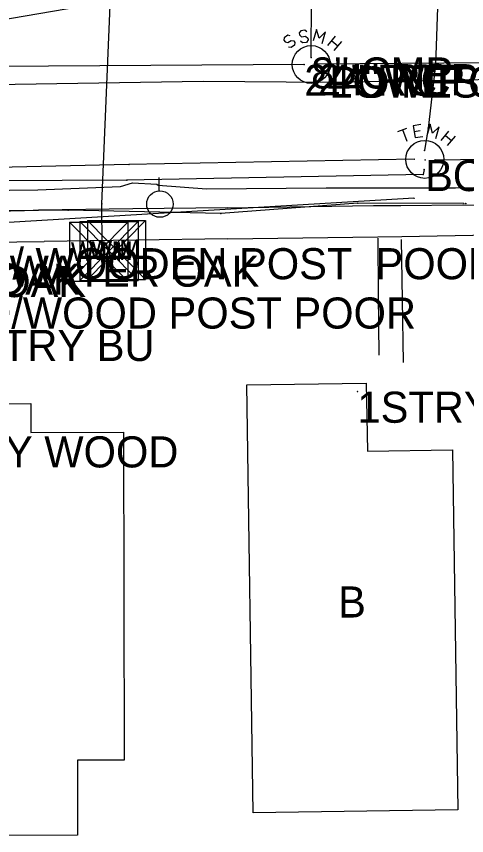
# Model space of a CAD drawing. Extents: x 1304270 to 1306561, y 1876019 to 1876752.
# Drawn here: x 1306184.9 to 1306257.2, y 1876292.6 to 1876424.3 of the extents above; entities that cross this region are included whole.
import ezdxf

# ---------------------------------------------------------------- set-up
doc = ezdxf.new("R2010")
doc.units = 0
for name, color, linetype in [('Default', 7, 'Continuous'), ('S_BUILDING', 7, 'Continuous'), ('S_BUILDING_ANNOT', 7, 'Continuous'), ('S_EDGE_PAVEMENT', 7, 'Continuous'), ('S_ELECTRIC_UTILITIES_ANNOT', 7, 'Continuous'), ('S_FENCE_ANNOT', 7, 'Continuous'), ('S_FIBER_OPTIC_CABLE', 7, 'Continuous'), ('S_GAS_UTILITIES', 7, 'Continuous'), ('S_MANHOLE_ANNOT', 7, 'Continuous'), ('S_MSC_PT_SYM', 7, 'Continuous'), ('S_PAVEMENT_CROWN', 7, 'Continuous'), ('S_SANITARY_SEWER', 7, 'Continuous'), ('S_SANITARY_SEWER_ANNOT', 7, 'Continuous'), ('S_SIDEWALK', 7, 'Continuous'), ('S_SURVEY_TEXT_ANNOT', 7, 'Continuous'), ('S_TELEPHONE_UTILITIES_ANNOT', 7, 'Continuous'), ('S_TREE_ANNOT', 7, 'Continuous'), ('S_UTILITY_POLE', 7, 'Continuous'), ('S_UTL_PT_SYM', 7, 'Continuous'), ('S_WATER_UTILITIES', 7, 'Continuous')]:
    doc.layers.add(name, color=color, linetype=linetype)

msp = doc.modelspace()

# ---------------------------------------------------------------- linework, layer by layer
at = {"layer": 'Default'}
msp.add_line((1305993.25, 1876391.55), (1306312.09, 1876445.88), dxfattribs=at)
at = {"layer": 'S_BUILDING'}
for points in [[(1306222.87, 1876296.29), (1306221.85, 1876365.09), (1306241.06, 1876365.38), (1306241.23, 1876354.44), (1306254.91, 1876354.64), (1306255.77, 1876296.78)], [(1306160.27, 1876302.99), (1306160.13, 1876356.76), (1306176.97, 1876356.8), (1306176.96, 1876362.05), (1306187.16, 1876362.08), (1306187.17, 1876357.43), (1306202.04, 1876357.47), (1306202.18, 1876304.76), (1306194.65, 1876304.74), (1306194.68, 1876292.7), (1306165.2, 1876292.62), (1306165.17, 1876303)]]:
    msp.add_lwpolyline(points, close=True, dxfattribs=at)
at = {"layer": 'S_EDGE_PAVEMENT'}
msp.add_lwpolyline([(1306165.48, 1876396.19), (1306188.31, 1876396.43), (1306201.55, 1876396.99), (1306203.51, 1876397.54), (1306207.41, 1876397.36), (1306207.63, 1876397.16), (1306215.41, 1876396.62), (1306234.61, 1876396.75), (1306255.38, 1876396.73), (1306279.47, 1876397.14), (1306280.07, 1876397.39), (1306281.48, 1876397.3), (1306281.94, 1876397.15), (1306288.47, 1876397.22), (1306311.84, 1876397.17), (1306330.84, 1876397.38), (1306332.77, 1876398.02), (1306334.38, 1876398.14), (1306335.31, 1876398.67), (1306336.28, 1876398.38), (1306337.28, 1876397.24), (1306338.63, 1876397.21), (1306354.54, 1876397.37)], dxfattribs=at)
at = {"layer": 'S_FIBER_OPTIC_CABLE'}
for p, q in [((1306252.78, 1876433.33), (1306252.18, 1876416.51)), ((1306252.18, 1876416.51), (1306251.01, 1876406.35)), ((1306251.01, 1876406.35), (1306250.43, 1876402.76)), ((1306248.77, 1876401.37), (1306202.94, 1876400.5)), ((1306252.11, 1876401.25), (1306297.1, 1876401.93)), ((1306202.94, 1876400.5), (1306143.64, 1876399.14)), ((1306250.33, 1876399.72), (1306250.18, 1876398.92)), ((1306250.18, 1876398.92), (1306202.59, 1876398)), ((1306202.59, 1876398), (1306143.62, 1876397.73)), ((1306248.72, 1876395.07), (1306106.88, 1876386.6))]:
    msp.add_line(p, q, dxfattribs=at)
at = {"layer": 'S_GAS_UTILITIES'}
for p, q in [((1306239.69, 1876394.28), (1306217.67, 1876392.63)), ((1306256.71, 1876394.26), (1306239.69, 1876394.28)), ((1306193.15, 1876393.15), (1306132.81, 1876392.65)), ((1306217.67, 1876392.63), (1306193.15, 1876393.15))]:
    msp.add_line(p, q, dxfattribs=at)
at = {"layer": 'S_MSC_PT_SYM'}
for points in [[(1306235.12, 1876416.26), (1306235.12, 1876416.31), (1306235.12, 1876416.26), (1306235.07, 1876416.26), (1306235.12, 1876416.26), (1306235.12, 1876416.21), (1306235.12, 1876416.26), (1306235.17, 1876416.26)], [(1306257.03, 1876394.23), (1306257.03, 1876394.28), (1306257.03, 1876394.23), (1306256.98, 1876394.23), (1306257.03, 1876394.23), (1306257.03, 1876394.18), (1306257.03, 1876394.23), (1306257.08, 1876394.23)], [(1306239.64, 1876363.99), (1306239.64, 1876364.04), (1306239.64, 1876363.99), (1306239.59, 1876363.99), (1306239.64, 1876363.99), (1306239.64, 1876363.94), (1306239.64, 1876363.99), (1306239.69, 1876363.99)]]:
    msp.add_lwpolyline(points, dxfattribs=at)
at = {"layer": 'S_PAVEMENT_CROWN'}
msp.add_lwpolyline([(1306053.64, 1876411.74), (1306078.45, 1876411.98), (1306096.34, 1876412.19), (1306114.22, 1876412.39), (1306129.3, 1876412.61), (1306144.38, 1876412.83), (1306159.45, 1876413.06), (1306174.53, 1876413.28), (1306194.7, 1876413.58), (1306214.87, 1876413.88), (1306234.9, 1876413.74), (1306250.98, 1876414.03), (1306267.06, 1876414.33), (1306289.97, 1876414.14), (1306302.49, 1876414.59), (1306315, 1876415.05), (1306334.8, 1876415.21), (1306354.59, 1876415.38)], dxfattribs=at)
at = {"layer": 'S_SANITARY_SEWER'}
for p, q in [((1306232.19, 1876417.72), (1306232.35, 1876438.98)), ((1306227.88, 1876420.88), (1306227.81, 1876420.49)), ((1306227.81, 1876420.49), (1306228, 1876420.22)), ((1306228.43, 1876421.27), (1306227.88, 1876420.88)), ((1306228.85, 1876421.19), (1306228.43, 1876421.27)), ((1306234.86, 1876419.64), (1306236.1, 1876421.11)), ((1306228, 1876420.22), (1306228.43, 1876420.1)), ((1306228.43, 1876420.1), (1306228.97, 1876420.45)), ((1306228.97, 1876419.29), (1306228.58, 1876419.37)), ((1306228.97, 1876420.45), (1306229.43, 1876420.37)), ((1306229.51, 1876419.68), (1306228.97, 1876419.29)), ((1306229.43, 1876420.37), (1306229.59, 1876420.1)), ((1306229.59, 1876420.1), (1306229.51, 1876419.68)), ((1306235.52, 1876420.41), (1306236.49, 1876419.6)), ((1306237.07, 1876420.3), (1306235.83, 1876418.82)), ((1306231.1, 1876416.56), (1305933.99, 1876414.7)), ((1306295.77, 1876417.07), (1306233.29, 1876416.64))]:
    msp.add_line(p, q, dxfattribs=at)
for points in [[(1306231.53, 1876421.81), (1306231.18, 1876422.08), (1306230.52, 1876422), (1306230.29, 1876421.65), (1306230.33, 1876421.34), (1306230.67, 1876421.03), (1306231.29, 1876421.15), (1306231.68, 1876420.84), (1306231.72, 1876420.53), (1306231.45, 1876420.14), (1306230.83, 1876420.06), (1306230.48, 1876420.34)], [(1306233.97, 1876419.95), (1306234.51, 1876421.81), (1306233.46, 1876420.8), (1306233.08, 1876422.23), (1306232.53, 1876420.37)]]:
    msp.add_lwpolyline(points, dxfattribs=at)
msp.add_circle((1306232.21, 1876416.58), 3.05, dxfattribs=at)
at = {"layer": 'S_SIDEWALK'}
for points in [[(1305952.26, 1876390.24), (1305960.41, 1876390.32), (1305966.26, 1876390.42), (1305977.98, 1876390.44), (1306001.88, 1876390.73), (1306025.78, 1876391.03), (1306046.11, 1876391.23), (1306059.51, 1876391.31), (1306072.82, 1876391.56), (1306093.38, 1876391.82), (1306107.91, 1876392.05), (1306108.42, 1876392.1), (1306122.83, 1876392.12), (1306134.63, 1876392.34), (1306141.58, 1876392.5), (1306158.19, 1876392.68), (1306174.81, 1876392.86), (1306188.4, 1876393.18)], [(1306218.73, 1876393.56), (1306203.56, 1876393.37), (1306188.4, 1876393.18)], [(1306218.73, 1876393.56), (1306242.23, 1876393.89), (1306246.62, 1876393.94), (1306256.53, 1876394.01), (1306278.18, 1876393.8), (1306278.83, 1876393.36), (1306281.72, 1876391.3), (1306281.69, 1876389.49)], [(1306218.81, 1876388.57), (1306242.93, 1876388.89), (1306246.78, 1876388.93), (1306260.98, 1876389.2), (1306270.25, 1876389.34), (1306277.02, 1876389.42), (1306281.65, 1876389.43)], [(1305946.19, 1876385.43), (1305960.07, 1876385.78), (1305966.36, 1876385.64), (1305978.22, 1876385.78), (1305997.78, 1876385.93), (1306001.65, 1876386), (1306023.78, 1876386.14), (1306028.37, 1876386.22), (1306037.11, 1876386.23), (1306046.79, 1876386.36), (1306058.81, 1876386.53), (1306072.25, 1876386.67), (1306085.1, 1876386.45), (1306093.62, 1876386.85), (1306109.56, 1876387.13), (1306122.97, 1876387.27), (1306134.64, 1876387.44), (1306141.92, 1876387.73), (1306161.2, 1876387.87), (1306180.48, 1876388.02), (1306189.34, 1876388.14)], [(1306218.81, 1876388.57), (1306204.07, 1876388.36), (1306189.34, 1876388.14)], [(1306242.9, 1876388.68), (1306242.95, 1876379.67), (1306243.09, 1876369.83)], [(1306247.03, 1876368.68), (1306246.89, 1876378.75), (1306246.73, 1876388.47)]]:
    msp.add_lwpolyline(points, dxfattribs=at)
at = {"layer": 'S_TELEPHONE_UTILITIES_ANNOT'}
for p, q in [((1306246.12, 1876405.82), (1306247.56, 1876406.37)), ((1306246.86, 1876406.13), (1306247.56, 1876404.27)), ((1306249.81, 1876406.95), (1306248.57, 1876406.71)), ((1306248.57, 1876406.71), (1306248.91, 1876404.82)), ((1306249.69, 1876405.94), (1306248.76, 1876405.78)), ((1306248.91, 1876404.82), (1306250.15, 1876405.01)), ((1306253.1, 1876404.39), (1306254.34, 1876405.86)), ((1306253.76, 1876405.16), (1306254.73, 1876404.35)), ((1306255.31, 1876405.05), (1306254.07, 1876403.58))]:
    msp.add_line(p, q, dxfattribs=at)
msp.add_lwpolyline([(1306252.21, 1876404.7), (1306252.75, 1876406.56), (1306251.7, 1876405.55), (1306251.32, 1876406.99), (1306250.77, 1876405.13)], dxfattribs=at)
msp.add_circle((1306250.45, 1876401.33), 3.05, dxfattribs=at)
at = {"layer": 'S_UTILITY_POLE'}
msp.add_line((1306207.79, 1876396.3), (1306207.79, 1876398.4), dxfattribs=at)
msp.add_circle((1306207.91, 1876394.15), 2.13, dxfattribs=at)
at = {"layer": 'S_UTL_PT_SYM'}
for points in [[(1306231.1, 1876416.56), (1306231.1, 1876416.61), (1306231.1, 1876416.56), (1306231.05, 1876416.56), (1306231.1, 1876416.56), (1306231.1, 1876416.51), (1306231.1, 1876416.56), (1306231.15, 1876416.56)], [(1306232.19, 1876417.72), (1306232.19, 1876417.77), (1306232.19, 1876417.72), (1306232.14, 1876417.72), (1306232.19, 1876417.72), (1306232.19, 1876417.67), (1306232.19, 1876417.72), (1306232.24, 1876417.72)], [(1306233.29, 1876416.64), (1306233.29, 1876416.69), (1306233.29, 1876416.64), (1306233.24, 1876416.64), (1306233.29, 1876416.64), (1306233.29, 1876416.59), (1306233.29, 1876416.64), (1306233.34, 1876416.64)], [(1306252.18, 1876416.51), (1306252.18, 1876416.56), (1306252.18, 1876416.51), (1306252.13, 1876416.51), (1306252.18, 1876416.51), (1306252.18, 1876416.46), (1306252.18, 1876416.51), (1306252.23, 1876416.51)], [(1306232.19, 1876416.37), (1306232.19, 1876416.42), (1306232.19, 1876416.37), (1306232.14, 1876416.37), (1306232.19, 1876416.37), (1306232.19, 1876416.32), (1306232.19, 1876416.37), (1306232.24, 1876416.37)], [(1306235.12, 1876416.26), (1306235.12, 1876416.31), (1306235.12, 1876416.26), (1306235.07, 1876416.26), (1306235.12, 1876416.26), (1306235.12, 1876416.21), (1306235.12, 1876416.26), (1306235.17, 1876416.26)], [(1306251.01, 1876406.35), (1306251.01, 1876406.4), (1306251.01, 1876406.35), (1306250.96, 1876406.35), (1306251.01, 1876406.35), (1306251.01, 1876406.3), (1306251.01, 1876406.35), (1306251.06, 1876406.35)], [(1306250.43, 1876402.76), (1306250.43, 1876402.81), (1306250.43, 1876402.76), (1306250.38, 1876402.76), (1306250.43, 1876402.76), (1306250.43, 1876402.71), (1306250.43, 1876402.76), (1306250.48, 1876402.76)], [(1306248.77, 1876401.37), (1306248.77, 1876401.42), (1306248.77, 1876401.37), (1306248.72, 1876401.37), (1306248.77, 1876401.37), (1306248.77, 1876401.32), (1306248.77, 1876401.37), (1306248.82, 1876401.37)], [(1306250.51, 1876401.23), (1306250.51, 1876401.28), (1306250.51, 1876401.23), (1306250.46, 1876401.23), (1306250.51, 1876401.23), (1306250.51, 1876401.18), (1306250.51, 1876401.23), (1306250.56, 1876401.23)], [(1306252.11, 1876401.25), (1306252.11, 1876401.3), (1306252.11, 1876401.25), (1306252.06, 1876401.25), (1306252.11, 1876401.25), (1306252.11, 1876401.2), (1306252.11, 1876401.25), (1306252.16, 1876401.25)], [(1306202.94, 1876400.5), (1306202.94, 1876400.55), (1306202.94, 1876400.5), (1306202.89, 1876400.5), (1306202.94, 1876400.5), (1306202.94, 1876400.45), (1306202.94, 1876400.5), (1306202.99, 1876400.5)], [(1306250.33, 1876399.72), (1306250.33, 1876399.77), (1306250.33, 1876399.72), (1306250.28, 1876399.72), (1306250.33, 1876399.72), (1306250.33, 1876399.67), (1306250.33, 1876399.72), (1306250.38, 1876399.72)], [(1306250.18, 1876398.92), (1306250.18, 1876398.97), (1306250.18, 1876398.92), (1306250.13, 1876398.92), (1306250.18, 1876398.92), (1306250.18, 1876398.87), (1306250.18, 1876398.92), (1306250.23, 1876398.92)], [(1306202.59, 1876398), (1306202.59, 1876398.05), (1306202.59, 1876398), (1306202.54, 1876398), (1306202.59, 1876398), (1306202.59, 1876397.95), (1306202.59, 1876398), (1306202.64, 1876398)], [(1306198.6, 1876394.2), (1306198.6, 1876394.25), (1306198.6, 1876394.2), (1306198.55, 1876394.2), (1306198.6, 1876394.2), (1306198.6, 1876394.15), (1306198.6, 1876394.2), (1306198.65, 1876394.2)], [(1306239.69, 1876394.28), (1306239.69, 1876394.33), (1306239.69, 1876394.28), (1306239.64, 1876394.28), (1306239.69, 1876394.28), (1306239.69, 1876394.23), (1306239.69, 1876394.28), (1306239.74, 1876394.28)], [(1306248.72, 1876395.07), (1306248.72, 1876395.12), (1306248.72, 1876395.07), (1306248.67, 1876395.07), (1306248.72, 1876395.07), (1306248.72, 1876395.02), (1306248.72, 1876395.07), (1306248.77, 1876395.07)], [(1306256.71, 1876394.26), (1306256.71, 1876394.31), (1306256.71, 1876394.26), (1306256.66, 1876394.26), (1306256.71, 1876394.26), (1306256.71, 1876394.21), (1306256.71, 1876394.26), (1306256.76, 1876394.26)], [(1306193.15, 1876393.15), (1306193.15, 1876393.2), (1306193.15, 1876393.15), (1306193.1, 1876393.15), (1306193.15, 1876393.15), (1306193.15, 1876393.1), (1306193.15, 1876393.15), (1306193.2, 1876393.15)], [(1306217.67, 1876392.63), (1306217.67, 1876392.68), (1306217.67, 1876392.63), (1306217.62, 1876392.63), (1306217.67, 1876392.63), (1306217.67, 1876392.58), (1306217.67, 1876392.63), (1306217.72, 1876392.63)], [(1306198.65, 1876387.44), (1306198.65, 1876387.49), (1306198.65, 1876387.44), (1306198.6, 1876387.44), (1306198.65, 1876387.44), (1306198.65, 1876387.39), (1306198.65, 1876387.44), (1306198.7, 1876387.44)]]:
    msp.add_lwpolyline(points, dxfattribs=at)
at = {"layer": 'S_WATER_UTILITIES'}
for p, q in [((1306198.6, 1876394.2), (1306200.22, 1876433.94)), ((1306198.65, 1876387.44), (1306198.6, 1876394.2)), ((1306196.26, 1876391.52), (1306205.6, 1876391.52)), ((1306196.26, 1876391.52), (1306196.26, 1876382.03)), ((1306196.26, 1876391.52), (1306205.6, 1876382.03)), ((1306205.6, 1876391.52), (1306196.26, 1876382.03)), ((1306205.6, 1876391.52), (1306205.6, 1876382.03)), ((1306193.39, 1876391.23), (1306202.73, 1876391.23)), ((1306193.39, 1876391.23), (1306193.39, 1876381.74)), ((1306193.39, 1876391.23), (1306202.73, 1876381.74)), ((1306202.73, 1876391.23), (1306193.39, 1876381.74)), ((1306195.06, 1876391.36), (1306204.4, 1876391.36)), ((1306195.06, 1876391.36), (1306195.06, 1876381.87)), ((1306195.06, 1876391.36), (1306204.4, 1876381.87)), ((1306204.4, 1876391.36), (1306195.06, 1876381.87)), ((1306202.73, 1876391.23), (1306202.73, 1876381.74)), ((1306204.4, 1876391.36), (1306204.4, 1876381.87)), ((1306193.39, 1876381.74), (1306202.73, 1876381.74)), ((1306195.06, 1876381.87), (1306204.4, 1876381.87)), ((1306196.26, 1876382.03), (1306205.6, 1876382.03))]:
    msp.add_line(p, q, dxfattribs=at)

# ---------------------------------------------------------------- texts
at = {"layer": 'S_BUILDING_ANNOT'}
for s, p in [('1 STRY WOOD', (1306164.07, 1876351.81)), ('B', (1306236.53, 1876327.68))]:
    msp.add_text(s, height=5, dxfattribs=at).set_placement(p)
at = {"layer": 'S_ELECTRIC_UTILITIES_ANNOT'}
msp.add_text('POINT ON ROAD UNDER LOW L', height=5, dxfattribs=at).set_placement((1306235.12, 1876411.26))
at = {"layer": 'S_FENCE_ANNOT'}
for s, p in [("3'WOODEN/ WOODEN POST  POOR", (1306148.39, 1876382.06)), ("2' WOOD/WOOD POST POOR", (1306155.64, 1876374.13))]:
    msp.add_text(s, height=5, dxfattribs=at).set_placement(p)
at = {"layer": 'S_MANHOLE_ANNOT'}
msp.add_text('BOTTOM OD HT', height=5, dxfattribs=at).set_placement((1306250.51, 1876396.23))
at = {"layer": 'S_SANITARY_SEWER_ANNOT'}
for s, p in [('24" RCP', (1306231.1, 1876411.56)), ('8" CMP', (1306232.19, 1876412.72)), ('24" RCP', (1306233.29, 1876411.64))]:
    msp.add_text(s, height=5, dxfattribs=at).set_placement(p)
at = {"layer": 'S_SURVEY_TEXT_ANNOT'}
for s, p in [('LOWEST UTILITY LINE', (1306235.12, 1876411.26)), ('ASPH DW TO 2 STRY BU', (1306128.29, 1876368.92)), ('1STRY BRICK', (1306239.64, 1876358.99))]:
    msp.add_text(s, height=5, dxfattribs=at).set_placement(p)
at = {"layer": 'S_TREE_ANNOT'}
for s, p in [('SPLIT 12" WATER OAK', (1306151.66, 1876380.86)), ('18" WATER OAK', (1306144.27, 1876379.19)), ('6" RED OAK', (1306157.15, 1876379.58))]:
    msp.add_text(s, height=5, dxfattribs=at).set_placement(p)
at = {"layer": 'S_WATER_UTILITIES'}
for p in [(1306193.6, 1876385), (1306195.27, 1876385.13), (1306196.47, 1876385.29)]:
    msp.add_text('W M', height=3, rotation=360, dxfattribs=at).set_placement(p)

doc.saveas('drawing.dxf')
